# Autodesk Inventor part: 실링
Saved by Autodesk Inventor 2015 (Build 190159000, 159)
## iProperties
Created: 2025-11
Part Number: 실링
Material: 일반
Document SubType Name: Modeling
Designer: user
Density: 1 g/cm^3
Appearance: 기본값
Author: user
Author: jhkim
Creation Date: 2025-10-31
Sending System: Autodesk Inventor 2026
Preprocessor: ST-DEVELOPER v20.1
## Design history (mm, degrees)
node "실링1"
node "솔리드3"
node "기준1"
